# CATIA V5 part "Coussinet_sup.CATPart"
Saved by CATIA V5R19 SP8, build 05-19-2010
Part number: Coussinet_sup
Revision: ANY
Definition: UNKNOWN
Nomenclature: 8
Source: Unknown
Bounding box of the stored display mesh (mm): x -6 to 5.672, y -6 to 1.955, z 0 to 13.5
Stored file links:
  D:\Documents\1_Travail\2- 2I2D\1 - Cours et TD\2- TD\3-TD Assemblage\Pompe AirMan\Coussinet_sup.CATPart
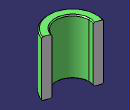
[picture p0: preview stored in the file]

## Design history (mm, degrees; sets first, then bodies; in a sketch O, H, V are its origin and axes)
Body1 "Chanfrein1" (main body)
  Solid1: solid without history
